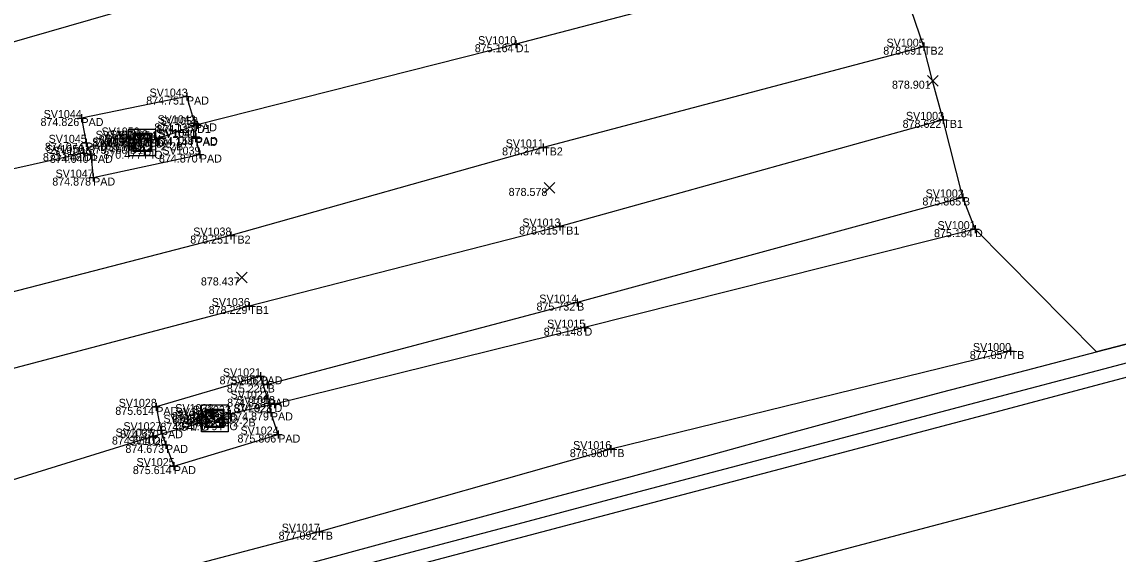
# Model space of a CAD drawing. Extents: x 2125299 to 2129212, y 713100 to 714300.
# Drawn here: x 2128517.6 to 2128654.5, y 714049.1 to 714115.5 of the extents above; entities that cross this region are included whole.
import ezdxf

# ---------------------------------------------------------------- set-up
doc = ezdxf.new("R2010")
doc.units = 0
for name, color, linetype in [('_CIVIL_CONSTRUCTION', 7, 'Continuous'), ('DR_X_Ditch', 7, 'Continuous'), ('DT_X_Terrain_Boundary', 7, 'Continuous'), ('PV_X_EOP', 7, 'Continuous'), ('PV_X_Shoulder_Rumble_Strip', 7, 'Continuous'), ('RD_X_Concrete_Pad', 7, 'Continuous'), ('RW_P_Esmt_TMP', 7, 'Continuous'), ('RW_X_CL_100_Bearings', 7, 'Continuous'), ('RW_X_CL_100_Cardinal_Points', 7, 'Continuous'), ('RW_X_Esmt_CH', 7, 'Continuous'), ('RW_X_Fee_WL', 7, 'Continuous'), ('SC_Scratch2', 7, 'Continuous'), ('SV_X_Break_Lines', 7, 'Continuous'), ('SV_X_Mon_Cells_Found', 7, 'Continuous'), ('SV_X_Text_Comment', 7, 'Continuous'), ('SV_X_Text_Elevation', 7, 'Continuous'), ('SV_X_Top_of_Bank', 7, 'Continuous')]:
    doc.layers.add(name, color=color, linetype=linetype)

msp = doc.modelspace()

# ---------------------------------------------------------------- linework, layer by layer
at = {"layer": '_CIVIL_CONSTRUCTION'}
msp.add_lwpolyline([(2128413.82, 713995), (2128428.32, 713998.85), (2128442.82, 714002.69), (2128457.31, 714006.53), (2128471.81, 714010.37), (2128486.31, 714014.22), (2128500.81, 714018.06), (2128515.31, 714021.9), (2128529.81, 714025.74), (2128544.31, 714029.58), (2128558.81, 714033.42), (2128573.31, 714037.26), (2128587.81, 714041.1), (2128602.31, 714044.94), (2128616.82, 714048.77), (2128631.32, 714052.61), (2128645.82, 714056.45), (2128660.32, 714060.29)], dxfattribs=at)
at = {"layer": 'DR_X_Ditch'}
msp.add_line((2128531.02, 714100.08), (2128531.02, 714100.08), dxfattribs=at)
for points in [[(2128625.93, 714124.99), (2128579.25, 714112.76), (2128539.45, 714102.67), (2128534.31, 714100.87)], [(2128525.29, 714099.16), (2128497.16, 714092.88), (2128436.33, 714076.51), (2128391.32, 714063.78), (2128330.37, 714048.18), (2128276.31, 714032.64)], [(2128636.61, 714089.66), (2128587.84, 714077.36), (2128549.11, 714067.82), (2128543.57, 714066.6)], [(2128539.96, 714065.48), (2128533.93, 714063.76), (2128504.91, 714054.76), (2128447.02, 714038.39), (2128399.37, 714025.09), (2128341.85, 714009.81), (2128283.6, 713994.68), (2128242.74, 713988.86), (2128205.78, 713990.56), (2128171.48, 713986), (2128143.07, 713980.05), (2128117.8, 713975.62)]]:
    msp.add_lwpolyline(points, dxfattribs=at)
at = {"layer": 'DT_X_Terrain_Boundary'}
msp.add_lwpolyline([(2128661.46, 714076.82), (2128651.78, 714074.32), (2128636.61, 714089.66), (2128635.11, 714093.62), (2128632.64, 714103.31), (2128631.32, 714108.2), (2128630.23, 714112.45), (2128625.93, 714124.99), (2128641.74, 714150.62), (2128651.4, 714153.18), (2128661.07, 714155.74)], dxfattribs=at)
at = {"layer": 'PV_X_EOP'}
msp.add_lwpolyline([(2128516.52, 714038.23), (2128526.19, 714040.77), (2128535.86, 714043.32), (2128545.53, 714045.87), (2128555.19, 714048.42), (2128564.85, 714051.02), (2128574.51, 714053.62), (2128584.16, 714056.22), (2128593.82, 714058.82), (2128603.47, 714061.44), (2128613.12, 714064.08), (2128622.76, 714066.71), (2128632.42, 714069.3), (2128642.1, 714071.81), (2128651.78, 714074.32), (2128661.46, 714076.82)], dxfattribs=at)
at = {"layer": 'PV_X_Shoulder_Rumble_Strip'}
msp.add_lwpolyline([(2128406.18, 714006.98), (2128420.68, 714010.82), (2128435.18, 714014.66), (2128449.68, 714018.5), (2128464.18, 714022.34), (2128478.68, 714026.18), (2128493.18, 714030.02), (2128507.68, 714033.86), (2128522.18, 714037.69), (2128536.68, 714041.53), (2128551.18, 714045.37), (2128565.68, 714049.2), (2128580.18, 714053.04), (2128594.68, 714056.88), (2128609.19, 714060.72), (2128623.69, 714064.55), (2128638.19, 714068.39), (2128652.69, 714072.23), (2128667.19, 714076.06)], dxfattribs=at)
at = {"layer": 'RD_X_Concrete_Pad'}
for points in [[(2128538.18, 714106.22), (2128525, 714103.54), (2128525.57, 714100.44), (2128526.16, 714098.94), (2128526.46, 714096.1), (2128539.79, 714098.98), (2128539.28, 714101.18), (2128539.18, 714102.88)], [(2128547.35, 714071.28), (2128534.35, 714067.47), (2128534.93, 714064.55), (2128535.56, 714062.72), (2128536.55, 714060.07), (2128549.59, 714064.01), (2128548.66, 714066.77), (2128548.3, 714068.49)]]:
    msp.add_lwpolyline(points, close=True, dxfattribs=at)
at = {"layer": 'RW_X_CL_100_Bearings'}
for p, q in [((2128532.59, 714102.16), (2128532.59, 714102.16)), ((2128531.59, 714100.5), (2128531.59, 714100.5)), ((2128532.59, 714101.5), (2128532.59, 714101.5)), ((2128532.59, 714100.5), (2128532.59, 714100.5)), ((2128532.59, 714100.5), (2128532.59, 714100.5)), ((2128532.59, 714100.5), (2128532.59, 714100.5)), ((2128533.59, 714100.5), (2128533.59, 714100.5)), ((2128532.59, 714099.5), (2128532.59, 714099.5)), ((2128532.59, 714098.83), (2128532.59, 714098.83)), ((2128541.64, 714067.7), (2128541.64, 714067.7)), ((2128540.64, 714066.03), (2128540.64, 714066.03)), ((2128541.64, 714067.03), (2128541.64, 714067.03)), ((2128541.64, 714066.03), (2128541.64, 714066.03)), ((2128541.64, 714066.03), (2128541.64, 714066.03)), ((2128541.64, 714066.03), (2128541.64, 714066.03)), ((2128542.64, 714066.03), (2128542.64, 714066.03)), ((2128541.64, 714065.03), (2128541.64, 714065.03)), ((2128541.64, 714064.36), (2128541.64, 714064.36))]:
    msp.add_line(p, q, dxfattribs=at)
at = {"layer": 'RW_X_CL_100_Cardinal_Points'}
for p, q in [((2128532.22, 714101.86), (2128532.22, 714100.86)), ((2128530.94, 714100.95), (2128531.94, 714100.95)), ((2128531.44, 714101.45), (2128531.44, 714100.45)), ((2128531.44, 714100.95), (2128531.44, 714100.95)), ((2128531.72, 714101.36), (2128532.72, 714101.36)), ((2128532.22, 714101.36), (2128532.22, 714101.36)), ((2128532.71, 714101.01), (2128533.71, 714101.01)), ((2128533.21, 714101.51), (2128533.21, 714100.51)), ((2128533.21, 714101.01), (2128533.21, 714101.01)), ((2128532.33, 714099.45), (2128533.33, 714099.45)), ((2128532.83, 714099.95), (2128532.83, 714098.95)), ((2128532.83, 714099.45), (2128532.83, 714099.45)), ((2128540.89, 714066.81), (2128541.89, 714066.81)), ((2128540.95, 714066.34), (2128541.95, 714066.34)), ((2128541.39, 714067.31), (2128541.39, 714066.31)), ((2128541.39, 714066.81), (2128541.39, 714066.81)), ((2128541.45, 714066.84), (2128541.45, 714065.84)), ((2128541.45, 714066.34), (2128541.45, 714066.34)), ((2128542.23, 714066.05), (2128542.23, 714065.05)), ((2128541.73, 714065.55), (2128542.73, 714065.55)), ((2128542.23, 714065.55), (2128542.23, 714065.55))]:
    msp.add_line(p, q, dxfattribs=at)
at = {"layer": 'SC_Scratch2'}
msp.add_lwpolyline([(2128407.09, 714005.42), (2128421.59, 714009.26), (2128436.09, 714013.1), (2128450.59, 714016.94), (2128465.09, 714020.78), (2128479.59, 714024.62), (2128494.09, 714028.45), (2128508.59, 714032.29), (2128523.09, 714036.13), (2128537.59, 714039.96), (2128552.09, 714043.8), (2128566.59, 714047.64), (2128581.09, 714051.48), (2128595.59, 714055.31), (2128610.09, 714059.15), (2128624.6, 714062.99), (2128639.1, 714066.82), (2128653.6, 714070.66), (2128668.1, 714074.5)], dxfattribs=at)
at = {"layer": 'SV_X_Break_Lines'}
msp.add_lwpolyline([(2128635.11, 714093.62), (2128586.91, 714080.49), (2128548.26, 714070.26)], dxfattribs=at)
at = {"layer": 'SV_X_Mon_Cells_Found'}
for p, q in [((2128578.75, 714112.76), (2128579.75, 714112.76)), ((2128579.25, 714113.26), (2128579.25, 714112.26)), ((2128579.25, 714112.76), (2128579.25, 714112.76)), ((2128630.23, 714112.95), (2128630.23, 714111.95)), ((2128629.73, 714112.45), (2128630.73, 714112.45)), ((2128630.23, 714112.45), (2128630.23, 714112.45)), ((2128537.68, 714106.22), (2128538.68, 714106.22)), ((2128538.18, 714106.72), (2128538.18, 714105.72)), ((2128538.18, 714106.22), (2128538.18, 714106.22)), ((2128524.5, 714103.54), (2128525.5, 714103.54)), ((2128525, 714104.04), (2128525, 714103.04)), ((2128525, 714103.54), (2128525, 714103.54)), ((2128539.18, 714103.38), (2128539.18, 714102.38)), ((2128539.45, 714103.17), (2128539.45, 714102.17)), ((2128632.14, 714103.31), (2128633.14, 714103.31)), ((2128632.64, 714103.81), (2128632.64, 714102.81)), ((2128632.64, 714103.31), (2128632.64, 714103.31)), ((2128538.68, 714102.88), (2128539.68, 714102.88)), ((2128538.95, 714102.67), (2128539.95, 714102.67)), ((2128539.18, 714102.88), (2128539.18, 714102.88)), ((2128539.28, 714101.68), (2128539.28, 714100.68)), ((2128539.45, 714102.67), (2128539.45, 714102.67)), ((2128525.07, 714100.44), (2128526.07, 714100.44)), ((2128525.57, 714100.94), (2128525.57, 714099.94)), ((2128525.57, 714100.44), (2128525.57, 714100.44)), ((2128531.02, 714100.58), (2128531.02, 714099.58)), ((2128533.81, 714100.87), (2128534.81, 714100.87)), ((2128534.31, 714101.37), (2128534.31, 714100.37)), ((2128534.31, 714100.87), (2128534.31, 714100.87)), ((2128538.75, 714101.04), (2128539.75, 714101.04)), ((2128538.78, 714101.18), (2128539.78, 714101.18)), ((2128539.25, 714101.54), (2128539.25, 714100.54)), ((2128539.25, 714101.04), (2128539.25, 714101.04)), ((2128539.28, 714101.18), (2128539.28, 714101.18)), ((2128582.67, 714100.37), (2128582.67, 714099.37)), ((2128524.79, 714099.16), (2128525.79, 714099.16)), ((2128525.29, 714099.66), (2128525.29, 714098.66)), ((2128525.29, 714099.16), (2128525.29, 714099.16)), ((2128525.66, 714098.94), (2128526.66, 714098.94)), ((2128526.16, 714099.44), (2128526.16, 714098.44)), ((2128526.16, 714098.94), (2128526.16, 714098.94)), ((2128530.52, 714100.08), (2128531.52, 714100.08)), ((2128531.02, 714100.08), (2128531.02, 714100.08)), ((2128539.29, 714098.98), (2128540.29, 714098.98)), ((2128539.79, 714099.48), (2128539.79, 714098.48)), ((2128539.79, 714098.98), (2128539.79, 714098.98)), ((2128582.17, 714099.87), (2128583.17, 714099.87)), ((2128582.67, 714099.87), (2128582.67, 714099.87)), ((2128525.96, 714096.1), (2128526.96, 714096.1)), ((2128526.46, 714096.6), (2128526.46, 714095.6)), ((2128526.46, 714096.1), (2128526.46, 714096.1)), ((2128634.61, 714093.62), (2128635.61, 714093.62)), ((2128635.11, 714094.12), (2128635.11, 714093.12)), ((2128635.11, 714093.62), (2128635.11, 714093.62)), ((2128543.67, 714089.36), (2128543.67, 714088.36)), ((2128584.24, 714089.99), (2128585.24, 714089.99)), ((2128584.74, 714090.49), (2128584.74, 714089.49)), ((2128584.74, 714089.99), (2128584.74, 714089.99)), ((2128636.11, 714089.66), (2128637.11, 714089.66)), ((2128636.61, 714090.16), (2128636.61, 714089.16)), ((2128636.61, 714089.66), (2128636.61, 714089.66)), ((2128543.17, 714088.86), (2128544.17, 714088.86)), ((2128543.67, 714088.86), (2128543.67, 714088.86)), ((2128545.47, 714080.06), (2128546.47, 714080.06)), ((2128545.97, 714080.56), (2128545.97, 714079.56)), ((2128545.97, 714080.06), (2128545.97, 714080.06)), ((2128586.41, 714080.49), (2128587.41, 714080.49)), ((2128586.91, 714080.99), (2128586.91, 714079.99)), ((2128586.91, 714080.49), (2128586.91, 714080.49)), ((2128587.34, 714077.36), (2128588.34, 714077.36)), ((2128587.84, 714077.86), (2128587.84, 714076.86)), ((2128587.84, 714077.36), (2128587.84, 714077.36)), ((2128640.56, 714074.44), (2128641.56, 714074.44)), ((2128641.06, 714074.94), (2128641.06, 714073.94)), ((2128641.06, 714074.44), (2128641.06, 714074.44)), ((2128547.35, 714071.78), (2128547.35, 714070.78)), ((2128546.85, 714071.28), (2128547.85, 714071.28)), ((2128547.35, 714071.28), (2128547.35, 714071.28)), ((2128547.76, 714070.26), (2128548.76, 714070.26)), ((2128548.26, 714070.76), (2128548.26, 714069.76)), ((2128548.26, 714070.26), (2128548.26, 714070.26)), ((2128548.3, 714068.99), (2128548.3, 714067.99)), ((2128533.85, 714067.47), (2128534.85, 714067.47)), ((2128534.35, 714067.97), (2128534.35, 714066.97)), ((2128534.35, 714067.47), (2128534.35, 714067.47)), ((2128547.8, 714068.49), (2128548.8, 714068.49)), ((2128548.3, 714068.49), (2128548.3, 714068.49)), ((2128548.61, 714067.82), (2128549.61, 714067.82)), ((2128549.11, 714068.32), (2128549.11, 714067.32)), ((2128549.11, 714067.82), (2128549.11, 714067.82)), ((2128539.96, 714065.98), (2128539.96, 714064.98)), ((2128543.07, 714066.6), (2128544.07, 714066.6)), ((2128543.57, 714067.1), (2128543.57, 714066.1)), ((2128543.57, 714066.6), (2128543.57, 714066.6)), ((2128548.16, 714066.77), (2128549.16, 714066.77)), ((2128548.66, 714067.27), (2128548.66, 714066.27)), ((2128548.66, 714066.77), (2128548.66, 714066.77)), ((2128534.93, 714065.05), (2128534.93, 714064.05)), ((2128539.46, 714065.48), (2128540.46, 714065.48)), ((2128539.96, 714065.48), (2128539.96, 714065.48)), ((2128533.43, 714063.76), (2128534.43, 714063.76)), ((2128533.93, 714064.26), (2128533.93, 714063.26)), ((2128533.93, 714063.76), (2128533.93, 714063.76)), ((2128534.43, 714064.55), (2128535.43, 714064.55)), ((2128534.93, 714064.55), (2128534.93, 714064.55)), ((2128549.09, 714064.01), (2128550.09, 714064.01)), ((2128549.59, 714064.51), (2128549.59, 714063.51)), ((2128549.59, 714064.01), (2128549.59, 714064.01)), ((2128535.06, 714062.72), (2128536.06, 714062.72)), ((2128535.56, 714063.22), (2128535.56, 714062.22)), ((2128535.56, 714062.72), (2128535.56, 714062.72)), ((2128590.62, 714062.19), (2128591.62, 714062.19)), ((2128591.12, 714062.69), (2128591.12, 714061.69)), ((2128591.12, 714062.19), (2128591.12, 714062.19)), ((2128536.55, 714060.57), (2128536.55, 714059.57)), ((2128536.05, 714060.07), (2128537.05, 714060.07)), ((2128536.55, 714060.07), (2128536.55, 714060.07)), ((2128554.7, 714052.38), (2128554.7, 714051.38)), ((2128554.2, 714051.88), (2128555.2, 714051.88)), ((2128554.7, 714051.88), (2128554.7, 714051.88))]:
    msp.add_line(p, q, dxfattribs=at)
at = {"layer": 'SV_X_Text_Comment'}
for p, q in [((2128531.44, 714099.88), (2128533.2, 714101.64)), ((2128531.44, 714101.02), (2128532.07, 714101.64)), ((2128532.04, 714099.35), (2128533.73, 714101.04)), ((2128533.17, 714099.35), (2128533.73, 714099.91)), ((2128540.5, 714065.42), (2128542.26, 714067.18)), ((2128540.5, 714066.55), (2128541.12, 714067.18)), ((2128541.1, 714064.89), (2128542.79, 714066.58)), ((2128542.23, 714064.89), (2128542.79, 714065.45))]:
    msp.add_line(p, q, dxfattribs=at)
for points in [[(2128530.92, 714102.16), (2128534.25, 714102.16), (2128534.25, 714098.83), (2128530.92, 714098.83)], [(2128531.44, 714101.64), (2128533.73, 714101.64), (2128533.73, 714099.35), (2128531.44, 714099.35)], [(2128531.59, 714101.5), (2128533.59, 714101.5), (2128533.59, 714099.5), (2128531.59, 714099.5)], [(2128539.98, 714067.7), (2128543.31, 714067.7), (2128543.31, 714064.36), (2128539.98, 714064.36)], [(2128540.5, 714067.18), (2128542.79, 714067.18), (2128542.79, 714064.89), (2128540.5, 714064.89)], [(2128540.64, 714067.03), (2128542.64, 714067.03), (2128542.64, 714065.03), (2128540.64, 714065.03)]]:
    msp.add_lwpolyline(points, close=True, dxfattribs=at)
at = {"layer": 'SV_X_Text_Elevation'}
for p, q in [((2128630.66, 714107.53), (2128631.99, 714108.87)), ((2128630.66, 714108.87), (2128631.99, 714107.53)), ((2128582.8, 714094.15), (2128584.13, 714095.48)), ((2128582.8, 714095.48), (2128584.13, 714094.15)), ((2128544.35, 714082.96), (2128545.69, 714084.3)), ((2128544.35, 714084.3), (2128545.69, 714082.96))]:
    msp.add_line(p, q, dxfattribs=at)
at = {"layer": 'SV_X_Top_of_Bank'}
for points in [[(2128621.75, 714139.89), (2128575.4, 714127.43), (2128536.54, 714118.82), (2128494.56, 714106.73), (2128494.59, 714106.74), (2128431.42, 714092.25), (2128387.26, 714080.92), (2128325.7, 714062.91), (2128270.25, 714048.29), (2128232.44, 714039), (2128192.57, 714028.85), (2128120.54, 714010.42)], [(2128630.23, 714112.45), (2128582.67, 714099.87), (2128543.67, 714088.86), (2128499.9, 714077.56), (2128440.42, 714062.73), (2128393.57, 714052.94), (2128334.24, 714034.3), (2128278.14, 714020.98), (2128236.99, 714017.4), (2128194.11, 714013.25), (2128178.62, 714010.69), (2128139.13, 714003.23), (2128093.27, 713996.96)], [(2128632.64, 714103.31), (2128584.74, 714089.99), (2128545.97, 714080.06), (2128501.31, 714068.27), (2128443.11, 714052.88), (2128397.55, 714033.79), (2128338.65, 714020.42), (2128280.89, 714002.86), (2128241.69, 713997.86), (2128197.7, 714003.21), (2128178.62, 714010.69)], [(2128641.06, 714074.44), (2128591.12, 714062.19), (2128554.7, 714051.88), (2128508.37, 714039.66), (2128452.53, 714024.9), (2128402.4, 714011.79), (2128346.92, 713996.07), (2128287.48, 713981.18), (2128247.17, 713969.96), (2128213.74, 713962.2), (2128176.95, 713953.14), (2128149.75, 713946.28), (2128088.07, 713932.71), (2128089.34, 713952.15), (2128089.79, 713973.52), (2128093.27, 713996.96)]]:
    msp.add_lwpolyline(points, dxfattribs=at)

# ---------------------------------------------------------------- texts
at = {"layer": 'RW_P_Esmt_TMP'}
for s, p in [('D1', (2128579.25, 714111.76)), ('TB2', (2128630.23, 714111.45)), ('PAD', (2128538.18, 714105.22)), ('PAD', (2128525, 714102.54)), ('TB1', (2128632.64, 714102.31)), ('PAD', (2128539.18, 714101.88)), ('D1', (2128539.45, 714101.67)), ('PAD', (2128525.57, 714099.44)), ('PIO', (2128531.44, 714099.95)), ('PIO', (2128532.22, 714100.36)), ('CB-2-2B', (2128532.59, 714099.5)), ('PIO', (2128533.21, 714100.01)), ('D1', (2128534.31, 714099.87)), ('PAD', (2128539.25, 714100.04)), ('PAD', (2128539.28, 714100.18)), ('D1', (2128525.29, 714098.16)), ('PAD', (2128526.16, 714097.94)), ('D1', (2128531.02, 714099.08)), ('PIO', (2128532.83, 714098.45)), ('PAD', (2128539.79, 714097.98)), ('TB2', (2128582.67, 714098.87)), ('PAD', (2128526.46, 714095.1)), ('B', (2128635.11, 714092.62)), ('TB1', (2128584.74, 714088.99)), ('D', (2128636.61, 714088.66)), ('TB2', (2128543.67, 714087.86)), ('TB1', (2128545.97, 714079.06)), ('B', (2128586.91, 714079.49)), ('D', (2128587.84, 714076.36)), ('TB', (2128641.06, 714073.44)), ('PAD', (2128547.35, 714070.28)), ('B', (2128548.26, 714069.26)), ('PAD', (2128534.35, 714066.47)), ('PAD', (2128548.3, 714067.49)), ('D', (2128549.11, 714066.82)), ('PIO', (2128541.39, 714065.81)), ('PIO', (2128541.45, 714065.34)), ('CB-2-2B', (2128541.64, 714065.03)), ('D', (2128543.57, 714065.6)), ('PAD', (2128548.66, 714065.77)), ('D', (2128539.96, 714064.48)), ('PIO', (2128542.23, 714064.55)), ('D', (2128533.93, 714062.76)), ('PAD', (2128534.93, 714063.55)), ('PAD', (2128549.59, 714063.01)), ('PAD', (2128535.56, 714061.72)), ('TB', (2128591.12, 714061.19)), ('PAD', (2128536.55, 714059.07)), ('TB', (2128554.7, 714050.88))]:
    msp.add_text(s, height=1, dxfattribs=at).set_placement(p)
at = {"layer": 'RW_X_Esmt_CH'}
for s, p in [('SV1010', (2128574.54, 714112.76)), ('SV1005', (2128625.56, 714112.45)), ('SV1043', (2128533.51, 714106.22)), ('SV1044', (2128520.28, 714103.54)), ('SV1003', (2128627.98, 714103.31)), ('SV1042', (2128534.51, 714102.88)), ('SV1053', (2128534.79, 714102.67)), ('SV1051', (2128526.77, 714100.95)), ('SV1050', (2128527.51, 714101.36)), ('SV1052', (2128528.54, 714101.01)), ('SV1054', (2128529.59, 714100.87)), ('SV1040', (2128534.54, 714101.04)), ('SV1041', (2128534.6, 714101.18)), ('SV1045', (2128520.9, 714100.44)), ('SV1055', (2128526.35, 714100.08)), ('SV1048', (2128527.89, 714100.5)), ('SV1049', (2128528.15, 714099.45)), ('SV1011', (2128577.99, 714099.87)), ('SV1056', (2128520.59, 714099.16)), ('SV1046', (2128521.46, 714098.94)), ('SV1039', (2128535.11, 714098.98)), ('SV1047', (2128521.77, 714096.1)), ('SV1002', (2128630.44, 714093.62)), ('SV1013', (2128580.07, 714089.99)), ('SV1001', (2128631.93, 714089.66)), ('SV1038', (2128538.97, 714088.86)), ('SV1036', (2128541.27, 714080.06)), ('SV1014', (2128582.19, 714080.49)), ('SV1015', (2128583.17, 714077.36)), ('SV1000', (2128636.35, 714074.44)), ('SV1021', (2128542.67, 714071.28)), ('SV1020', (2128543.55, 714070.26)), ('SV1022', (2128543.63, 714068.49)), ('SV1018', (2128544.41, 714067.82)), ('SV1028', (2128529.65, 714067.47)), ('SV1032', (2128536.72, 714066.81)), ('SV1031', (2128536.77, 714066.34)), ('SV1033', (2128538.9, 714066.6)), ('SV1023', (2128544, 714066.77)), ('SV1034', (2128535.24, 714065.48)), ('SV1029', (2128536.96, 714066.03)), ('SV1030', (2128537.52, 714065.55)), ('SV1035', (2128529.26, 714063.76)), ('SV1027', (2128530.24, 714064.55)), ('SV1024', (2128544.87, 714064.01)), ('SV1026', (2128530.85, 714062.72)), ('SV1016', (2128586.41, 714062.19)), ('SV1025', (2128531.88, 714060.07)), ('SV1017', (2128550.01, 714051.88))]:
    msp.add_text(s, height=1, dxfattribs=at).set_placement(p)
at = {"layer": 'RW_X_Fee_WL'}
for s, p in [('875.164', (2128574.13, 714111.76)), ('878.691', (2128625.15, 714111.45)), ('878.901', (2128626.24, 714107.2)), ('874.751', (2128533.09, 714105.22)), ('874.826', (2128519.89, 714102.54)), ('878.622', (2128627.57, 714102.31)), ('874.135', (2128534.11, 714101.88)), ('874.117', (2128534.36, 714101.67)), ('874.074', (2128520.44, 714099.44)), ('870.377', (2128526.35, 714099.95)), ('870.305', (2128527.15, 714100.36)), ('873.716', (2128527.48, 714099.5)), ('870.385', (2128528.14, 714100.01)), ('873.741', (2128529.23, 714099.87)), ('874.144', (2128534.13, 714100.04)), ('874.159', (2128534.2, 714100.18)), ('873.848', (2128520.19, 714098.16)), ('874.040', (2128521.05, 714097.94)), ('873.780', (2128525.9, 714099.08)), ('870.477', (2128527.74, 714098.45)), ('874.870', (2128534.68, 714097.98)), ('878.374', (2128577.54, 714098.87)), ('874.878', (2128521.36, 714095.1)), ('878.578', (2128578.36, 714093.81)), ('875.865', (2128630.04, 714092.62)), ('878.315', (2128579.67, 714088.99)), ('875.184', (2128631.49, 714088.66)), ('878.251', (2128538.59, 714087.86)), ('878.437', (2128539.92, 714082.63)), ('878.229', (2128540.89, 714079.06)), ('875.732', (2128581.84, 714079.49)), ('875.148', (2128582.74, 714076.36)), ('877.057', (2128635.96, 714073.44)), ('875.826', (2128542.25, 714070.28)), ('875.226', (2128543.16, 714069.26)), ('875.614', (2128529.23, 714066.47)), ('874.878', (2128543.2, 714067.49)), ('874.928', (2128544.01, 714066.82)), ('871.097', (2128536.3, 714065.81)), ('871.476', (2128536.35, 714065.34)), ('874.545', (2128536.57, 714065.03)), ('874.594', (2128538.44, 714065.6)), ('874.879', (2128543.58, 714065.77)), ('874.547', (2128534.87, 714064.48)), ('871.679', (2128537.15, 714064.55)), ('874.654', (2128528.81, 714062.76)), ('874.570', (2128529.82, 714063.55)), ('875.806', (2128544.49, 714063.01)), ('874.673', (2128530.49, 714061.72)), ('876.980', (2128586, 714061.19)), ('875.614', (2128531.42, 714059.07)), ('877.092', (2128549.63, 714050.88))]:
    msp.add_text(s, height=1, dxfattribs=at).set_placement(p)

doc.saveas('drawing.dxf')
